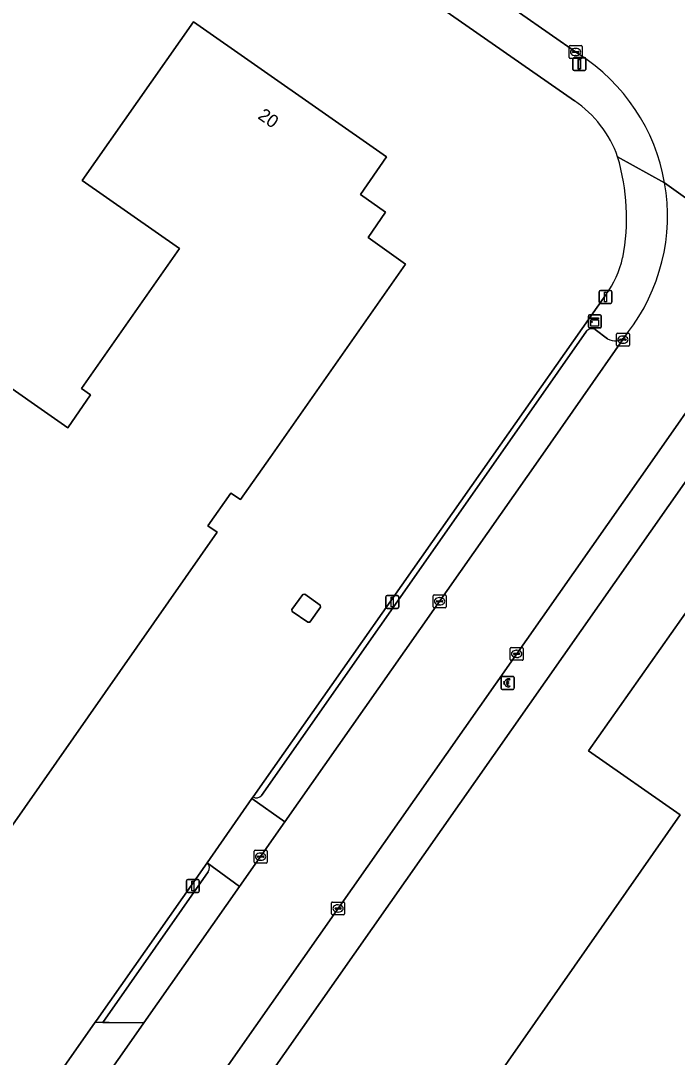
# Model space of a CAD drawing. Extents: x 155018 to 156648, y 383979 to 385733.
# Drawn here: x 155378.9 to 155429.7, y 384953.5 to 385033.8 of the extents above; entities that cross this region are included whole.
import ezdxf

# ---------------------------------------------------------------- set-up
doc = ezdxf.new("R2010")
doc.units = 0
for name, color, linetype in [('IMGEO_Betaalautomaat', 7, 'Continuous'), ('IMGEO_Erf', 7, 'Continuous'), ('IMGEO_Kast', 7, 'Continuous'), ('IMGEO_Kolk', 7, 'Continuous'), ('IMGEO_Lichtmast', 7, 'Continuous'), ('IMGEO_Pand', 7, 'Continuous'), ('IMGEO_Pand_nummerreeks', 7, 'Continuous'), ('IMGEO_Parkeervlak_open', 7, 'Continuous'), ('IMGEO_Rijbaan_lokaal_gesloten', 7, 'Continuous'), ('IMGEO_Rijbaan_lokaal_open', 7, 'Continuous'), ('IMGEO_Voetpad_open', 7, 'Continuous')]:
    doc.layers.add(name, color=color, linetype=linetype)

msp = doc.modelspace()

# ---------------------------------------------------------------- linework, layer by layer
at = {"layer": 'IMGEO_Betaalautomaat'}
for p, q in [((155416.064, 384982.106), (155416.064, 384982.947)), ((155416.064, 384982.947), (155416.064, 384982.106)), ((155416.139, 384983.03), (155416.98, 384983.03)), ((155416.98, 384983.03), (155416.139, 384983.03)), ((155416.726, 384982.835), (155416.709, 384982.735)), ((155417.063, 384982.956), (155417.063, 384982.115)), ((155417.063, 384982.115), (155417.063, 384982.956)), ((155416.989, 384982.031), (155416.148, 384982.031)), ((155416.148, 384982.031), (155416.989, 384982.031)), ((155416.347, 384982.494), (155416.347, 384982.562)), ((155416.468, 384982.562), (155416.468, 384982.494)), ((155416.713, 384982.329), (155416.735, 384982.242))]:
    msp.add_line(p, q, dxfattribs=at)
for points in [[(155416.347, 384982.562), (155416.278, 384982.562), (155416.278, 384982.631), (155416.357, 384982.631)], [(155416.352, 384982.425), (155416.278, 384982.425), (155416.278, 384982.494), (155416.347, 384982.494)], [(155416.479, 384982.631), (155416.626, 384982.631), (155416.626, 384982.562), (155416.468, 384982.562)], [(155416.468, 384982.494), (155416.626, 384982.494), (155416.626, 384982.425), (155416.482, 384982.425)]]:
    msp.add_lwpolyline(points, dxfattribs=at)
for centre, radius, start, end in [((155416.142, 384982.953), 0.0779, 92.4484, 184.28452), ((155416.142, 384982.953), 0.0779, 92.4484, 184.28452), ((155416.64, 384982.555), 0.293, 73.01398, 165.01395), ((155416.986, 384982.953), 0.0779, 2.4484, 94.28452), ((155416.986, 384982.953), 0.0779, 2.4484, 94.28452), ((155416.142, 384982.109), 0.0779, 182.4484, 274.28452), ((155416.142, 384982.109), 0.0779, 182.4484, 274.28452), ((155416.613, 384982.48), 0.267, 191.80956, 297.03891), ((155416.646, 384982.568), 0.179, 69.32359, 159.56827), ((155416.646, 384982.495), 0.179, 202.76249, 291.86925), ((155416.986, 384982.109), 0.0779, 272.4484, 4.28452), ((155416.986, 384982.109), 0.0779, 272.4484, 4.28452)]:
    msp.add_arc(centre, radius, start, end, dxfattribs=at)
at = {"layer": 'IMGEO_Erf'}
for points in [[(155421.752, 385027.617), (155394.996, 385046.278), (155391.028, 385049.046), (155385.591, 385052.838), (155385.399, 385052.961), (155380.151, 385056.63), (155341.349, 385083.758), (155335.658, 385087.641), (155324.962, 385095.154), (155317.041, 385100.717), (155292.001, 385118.303), (155289.287, 385120.198), (155288.53, 385120.608), (155288.137, 385120.826), (155288.024, 385120.665), (155281.331, 385125.336), (155281.524, 385125.635), (155276.133, 385129.546), (155243.348, 385152.362), (155212.561, 385173.841)], [(155415.322, 385000), (155424.161, 385012.596)], [(155435.235, 385005.097), (155431.663, 385000), (155395.301, 384948.119), (155392.871, 384944.656), (155386.964, 384936.206), (155382.993, 384930.585), (155380.633, 384927.147), (155378.001, 384923.366), (155376.2, 384920.796), (155354.955, 384890.532), (155337.874, 384866.058)], [(155327.011, 384874.232), (155360.91, 384922.726), (155360.915, 384922.733), (155375.747, 384943.951), (155375.951, 384943.821), (155379.854, 384949.392), (155384.652, 384956.241), (155384.747, 384956.376), (155393.303, 384968.589), (155396.774, 384973.585), (155396.869, 384973.702), (155415.322, 385000)]]:
    msp.add_lwpolyline(points, dxfattribs=at)
for points in [[(155351.349, 384984.37), (155362.289, 385000), (155370.017, 385011.042), (155382.518, 385002.292), (155384.294, 385004.83), (155383.582, 385005.329), (155391.174, 385016.176), (155383.643, 385021.448), (155392.242, 385033.743), (155407.202, 385023.273), (155405.168, 385020.366), (155407.118, 385018.987), (155405.763, 385017.027), (155408.659, 385014.971), (155398.182, 385000), (155395.894, 384996.73), (155395.145, 384997.227), (155393.369, 384994.694), (155394.096, 384994.197), (155375.417, 384967.495), (155365.992, 384954.131), (155341.937, 384971.002)], [(155437.272, 384901.403), (155412.162, 384919.023), (155417.316, 384926.358), (155404.257, 384935.52), (155429.931, 384972.307), (155422.839, 384977.259), (155438.817, 385000), (155439.816, 385001.422), (155441.823, 385000), (155445.207, 384997.603), (155444.284, 384997.18), (155444.973, 384993.255), (155452.396, 384994.446), (155452.453, 384994.103), (155450.711, 384993.78), (155463.948, 384984.474), (155458.937, 384977.31), (155471.068, 384968.794), (155464.079, 384958.829), (155473.162, 384952.461)], [(155399.897, 384988.059), (155399.873, 384988.22), (155400.711, 384989.382), (155400.863, 384989.396), (155402.049, 384988.541), (155402.076, 384988.399), (155401.268, 384987.233), (155401.109, 384987.228)]]:
    msp.add_lwpolyline(points, close=True, dxfattribs=at)
for centre, radius, start, end in [((155416.885, 385020.442), 8.67, 37.457, 55.84789), ((155416.874, 385020.421), 8.691, 19.17556, 37.52396), ((155409.507, 385018.585), 16.267, 348.93981, 16.76159), ((155418.417, 385016.955), 7.21, 322.8033, 348.06519)]:
    msp.add_arc(centre, radius, start, end, dxfattribs=at)
at = {"layer": 'IMGEO_Kast'}
for p, q in [((155422.817, 385010.103), (155422.817, 385010.944)), ((155422.817, 385010.944), (155422.817, 385010.103)), ((155422.892, 385011.028), (155423.733, 385011.028)), ((155423.733, 385011.028), (155422.892, 385011.028)), ((155423.817, 385010.953), (155423.817, 385010.112)), ((155423.817, 385010.112), (155423.817, 385010.953)), ((155423.742, 385010.028), (155422.901, 385010.028)), ((155422.901, 385010.028), (155423.742, 385010.028))]:
    msp.add_line(p, q, dxfattribs=at)
for points in [[(155423.012, 385010.818), (155423.612, 385010.818), (155423.612, 385010.733), (155423.012, 385010.733), (155423.012, 385010.818)], [(155423.012, 385010.643), (155423.612, 385010.643), (155423.612, 385010.154), (155423.012, 385010.154), (155423.012, 385010.643)]]:
    msp.add_lwpolyline(points, dxfattribs=at)
msp.add_circle((155423.096, 385010.492), 0.0377, dxfattribs=at)
for centre, start, end in [((155422.895, 385010.95), 92.4484, 184.28452), ((155422.895, 385010.95), 92.4484, 184.28452), ((155423.739, 385010.95), 2.4484, 94.28452), ((155423.739, 385010.95), 2.4484, 94.28452), ((155422.895, 385010.106), 182.4484, 274.28452), ((155422.895, 385010.106), 182.4484, 274.28452), ((155423.739, 385010.106), 272.4484, 4.28452), ((155423.739, 385010.106), 272.4484, 4.28452)]:
    msp.add_arc(centre, 0.0779, start, end, dxfattribs=at)
at = {"layer": 'IMGEO_Kolk'}
for p, q in [((155421.328, 385030.967), (155421.328, 385031.819)), ((155421.403, 385031.893), (155422.255, 385031.893)), ((155422.329, 385031.819), (155422.329, 385030.967)), ((155421.587, 385031.387), (155421.587, 385031.399)), ((155422.025, 385031.35), (155421.627, 385031.35)), ((155421.63, 385031.436), (155422.028, 385031.436)), ((155421.839, 385031.113), (155421.814, 385031.113)), ((155421.816, 385031.673), (155421.841, 385031.673)), ((155422.071, 385031.399), (155422.071, 385031.387)), ((155422.255, 385030.893), (155421.403, 385030.893)), ((155424.989, 385008.692), (155424.989, 385009.544)), ((155425.064, 385009.618), (155425.916, 385009.618)), ((155425.477, 385009.398), (155425.502, 385009.398)), ((155425.99, 385009.544), (155425.99, 385008.692)), ((155425.916, 385008.618), (155425.064, 385008.618)), ((155425.248, 385009.112), (155425.248, 385009.124)), ((155425.686, 385009.075), (155425.288, 385009.075)), ((155425.291, 385009.161), (155425.689, 385009.161)), ((155425.5, 385008.838), (155425.475, 385008.838)), ((155425.732, 385009.124), (155425.732, 385009.112)), ((155410.798, 384988.43), (155410.798, 384989.282)), ((155410.873, 384989.356), (155411.725, 384989.356)), ((155411.799, 384989.282), (155411.799, 384988.43)), ((155411.057, 384988.85), (155411.057, 384988.862)), ((155411.495, 384988.813), (155411.097, 384988.813)), ((155411.1, 384988.899), (155411.498, 384988.899)), ((155411.309, 384988.576), (155411.284, 384988.576)), ((155411.286, 384989.136), (155411.311, 384989.136)), ((155411.541, 384988.862), (155411.541, 384988.85)), ((155411.725, 384988.356), (155410.873, 384988.356)), ((155416.766, 384984.355), (155416.766, 384985.207)), ((155416.841, 384985.281), (155417.693, 384985.281)), ((155417.767, 384985.207), (155417.767, 384984.355)), ((155417.025, 384984.775), (155417.025, 384984.787)), ((155417.463, 384984.738), (155417.065, 384984.738)), ((155417.068, 384984.824), (155417.466, 384984.824)), ((155417.277, 384984.501), (155417.252, 384984.501)), ((155417.254, 384985.061), (155417.279, 384985.061)), ((155417.509, 384984.787), (155417.509, 384984.775)), ((155417.693, 384984.281), (155416.841, 384984.281)), ((155396.945, 384968.648), (155396.945, 384969.5)), ((155397.02, 384969.574), (155397.872, 384969.574)), ((155397.433, 384969.354), (155397.458, 384969.354)), ((155397.946, 384969.5), (155397.946, 384968.648)), ((155397.872, 384968.574), (155397.02, 384968.574)), ((155397.204, 384969.068), (155397.204, 384969.08)), ((155397.642, 384969.031), (155397.244, 384969.031)), ((155397.247, 384969.117), (155397.645, 384969.117)), ((155397.456, 384968.794), (155397.431, 384968.794)), ((155397.688, 384969.08), (155397.688, 384969.068)), ((155402.944, 384964.632), (155402.944, 384965.484)), ((155403.019, 384965.558), (155403.871, 384965.558)), ((155403.432, 384965.338), (155403.457, 384965.338)), ((155403.945, 384965.484), (155403.945, 384964.632)), ((155403.871, 384964.558), (155403.019, 384964.558)), ((155403.203, 384965.052), (155403.203, 384965.064)), ((155403.641, 384965.015), (155403.243, 384965.015)), ((155403.246, 384965.101), (155403.644, 384965.101)), ((155403.455, 384964.778), (155403.43, 384964.778)), ((155403.687, 384965.064), (155403.687, 384965.052))]:
    msp.add_line(p, q, dxfattribs=at)
for points in [[(155421.328, 385030.967), (155421.328, 385031.819)], [(155421.403, 385031.893), (155422.255, 385031.893)], [(155422.329, 385031.819), (155422.329, 385030.967)], [(155422.255, 385030.893), (155421.403, 385030.893)], [(155424.989, 385008.692), (155424.989, 385009.544)], [(155425.064, 385009.618), (155425.916, 385009.618)], [(155425.99, 385009.544), (155425.99, 385008.692)], [(155425.916, 385008.618), (155425.064, 385008.618)], [(155410.798, 384988.43), (155410.798, 384989.282)], [(155410.873, 384989.356), (155411.725, 384989.356)], [(155411.799, 384989.282), (155411.799, 384988.43)], [(155411.725, 384988.356), (155410.873, 384988.356)], [(155416.766, 384984.355), (155416.766, 384985.207)], [(155416.841, 384985.281), (155417.693, 384985.281)], [(155417.767, 384985.207), (155417.767, 384984.355)], [(155417.693, 384984.281), (155416.841, 384984.281)], [(155396.945, 384968.648), (155396.945, 384969.5)], [(155397.02, 384969.574), (155397.872, 384969.574)], [(155397.946, 384969.5), (155397.946, 384968.648)], [(155397.872, 384968.574), (155397.02, 384968.574)], [(155402.944, 384964.632), (155402.944, 384965.484)], [(155403.019, 384965.558), (155403.871, 384965.558)], [(155403.945, 384965.484), (155403.945, 384964.632)], [(155403.871, 384964.558), (155403.019, 384964.558)]]:
    msp.add_lwpolyline(points, dxfattribs=at)
for centre, radius, start, end in [((155421.405, 385031.817), 0.0765, 91.55205, 178.44795), ((155421.405, 385031.817), 0.0765, 91.55205, 178.44795), ((155422.253, 385031.817), 0.0765, 1.55205, 88.44795), ((155422.253, 385031.817), 0.0765, 1.55205, 88.44795), ((155421.405, 385030.969), 0.0765, 181.55205, 268.44795), ((155421.405, 385030.969), 0.0765, 181.55205, 268.44795), ((155421.627, 385031.396), 0.0403, 85.87752, 175.75265), ((155421.624, 385031.386), 0.0366, 178.93798, 274.71019), ((155422.028, 385031.393), 0.043, 264.86636, 352.45326), ((155422.032, 385031.398), 0.0386, 1.73085, 96.63898), ((155422.253, 385030.969), 0.0765, 271.55205, 358.44795), ((155422.253, 385030.969), 0.0765, 271.55205, 358.44795), ((155425.066, 385009.542), 0.0765, 91.55205, 178.44795), ((155425.066, 385009.542), 0.0765, 91.55205, 178.44795), ((155425.914, 385009.542), 0.0765, 1.55205, 88.44795), ((155425.914, 385009.542), 0.0765, 1.55205, 88.44795), ((155425.066, 385008.694), 0.0765, 181.55205, 268.44795), ((155425.066, 385008.694), 0.0765, 181.55205, 268.44795), ((155425.288, 385009.121), 0.0403, 85.87752, 175.75265), ((155425.285, 385009.111), 0.0366, 178.93798, 274.71019), ((155425.689, 385009.118), 0.043, 264.86636, 352.45326), ((155425.693, 385009.123), 0.0386, 1.73085, 96.63898), ((155425.914, 385008.694), 0.0765, 271.55205, 358.44795), ((155425.914, 385008.694), 0.0765, 271.55205, 358.44795), ((155410.875, 384989.28), 0.0765, 91.55205, 178.44795), ((155410.875, 384989.28), 0.0765, 91.55205, 178.44795), ((155411.723, 384989.28), 0.0765, 1.55205, 88.44795), ((155411.723, 384989.28), 0.0765, 1.55205, 88.44795), ((155410.875, 384988.432), 0.0765, 181.55205, 268.44795), ((155410.875, 384988.432), 0.0765, 181.55205, 268.44795), ((155411.097, 384988.859), 0.0403, 85.87752, 175.75265), ((155411.094, 384988.849), 0.0366, 178.93798, 274.71019), ((155411.498, 384988.856), 0.043, 264.86636, 352.45326), ((155411.502, 384988.861), 0.0386, 1.73085, 96.63898), ((155411.723, 384988.432), 0.0765, 271.55205, 358.44795), ((155411.723, 384988.432), 0.0765, 271.55205, 358.44795), ((155416.843, 384985.205), 0.0765, 91.55205, 178.44795), ((155416.843, 384985.205), 0.0765, 91.55205, 178.44795), ((155417.691, 384985.205), 0.0765, 1.55205, 88.44795), ((155417.691, 384985.205), 0.0765, 1.55205, 88.44795), ((155417.065, 384984.784), 0.0403, 85.87752, 175.75265), ((155417.062, 384984.774), 0.0366, 178.93798, 274.71019), ((155417.466, 384984.781), 0.043, 264.86636, 352.45326), ((155417.47, 384984.786), 0.0386, 1.73085, 96.63898), ((155416.843, 384984.357), 0.0765, 181.55205, 268.44795), ((155416.843, 384984.357), 0.0765, 181.55205, 268.44795), ((155417.691, 384984.357), 0.0765, 271.55205, 358.44795), ((155417.691, 384984.357), 0.0765, 271.55205, 358.44795), ((155397.022, 384969.498), 0.0765, 91.55205, 178.44795), ((155397.022, 384969.498), 0.0765, 91.55205, 178.44795), ((155397.87, 384969.498), 0.0765, 1.55205, 88.44795), ((155397.87, 384969.498), 0.0765, 1.55205, 88.44795), ((155397.022, 384968.65), 0.0765, 181.55205, 268.44795), ((155397.022, 384968.65), 0.0765, 181.55205, 268.44795), ((155397.244, 384969.077), 0.0403, 85.87752, 175.75265), ((155397.241, 384969.067), 0.0366, 178.93798, 274.71019), ((155397.645, 384969.074), 0.043, 264.86636, 352.45326), ((155397.649, 384969.079), 0.0386, 1.73085, 96.63898), ((155397.87, 384968.65), 0.0765, 271.55205, 358.44795), ((155397.87, 384968.65), 0.0765, 271.55205, 358.44795), ((155403.021, 384965.482), 0.0765, 91.55205, 178.44795), ((155403.021, 384965.482), 0.0765, 91.55205, 178.44795), ((155403.869, 384965.482), 0.0765, 1.55205, 88.44795), ((155403.869, 384965.482), 0.0765, 1.55205, 88.44795), ((155403.021, 384964.634), 0.0765, 181.55205, 268.44795), ((155403.021, 384964.634), 0.0765, 181.55205, 268.44795), ((155403.243, 384965.061), 0.0403, 85.87752, 175.75265), ((155403.24, 384965.051), 0.0366, 178.93798, 274.71019), ((155403.644, 384965.058), 0.043, 264.86636, 352.45326), ((155403.648, 384965.063), 0.0386, 1.73085, 96.63898), ((155403.869, 384964.634), 0.0765, 271.55205, 358.44795), ((155403.869, 384964.634), 0.0765, 271.55205, 358.44795)]:
    msp.add_arc(centre, radius, start, end, dxfattribs=at)
for centre, major_axis, ratio, start_param, end_param in [((155421.815, 385031.393), (-0.387, 0.002), 0.722429, 4.712389, 7.853982), ((155421.84, 385031.393), (-0.39, 0.002), 0.717154, 1.570796, 4.712389), ((155425.476, 385009.118), (-0.387, 0.002), 0.722429, 4.712389, 7.853982), ((155425.501, 385009.118), (-0.39, 0.002), 0.717154, 1.570796, 4.712389), ((155411.285, 384988.856), (-0.387, 0.002), 0.722429, 4.712389, 7.853982), ((155411.31, 384988.856), (-0.39, 0.002), 0.717154, 1.570796, 4.712389), ((155417.253, 384984.781), (-0.387, 0.002), 0.722429, 4.712389, 7.853982), ((155417.278, 384984.781), (-0.39, 0.002), 0.717154, 1.570796, 4.712389), ((155397.432, 384969.074), (-0.387, 0.002), 0.722429, 4.712389, 7.853982), ((155397.457, 384969.074), (-0.39, 0.002), 0.717154, 1.570796, 4.712389), ((155403.431, 384965.058), (-0.387, 0.002), 0.722429, 4.712389, 7.853982), ((155403.456, 384965.058), (-0.39, 0.002), 0.717154, 1.570796, 4.712389)]:
    msp.add_ellipse(centre, major_axis=major_axis, ratio=ratio, start_param=start_param, end_param=end_param, dxfattribs=at)
at = {"layer": 'IMGEO_Lichtmast'}
for p, q in [((155421.727, 385030.974), (155422.517, 385030.974)), ((155422.517, 385030.974), (155421.727, 385030.974)), ((155421.618, 385030.053), (155421.618, 385030.853)), ((155421.618, 385030.853), (155421.618, 385030.053)), ((155421.627, 385030.074), (155421.627, 385030.874)), ((155421.627, 385030.874), (155421.627, 385030.074)), ((155421.718, 385030.953), (155422.508, 385030.953)), ((155422.508, 385030.953), (155421.718, 385030.953)), ((155422.608, 385030.853), (155422.608, 385030.053)), ((155422.608, 385030.053), (155422.608, 385030.853)), ((155422.617, 385030.874), (155422.617, 385030.074)), ((155422.617, 385030.074), (155422.617, 385030.874)), ((155422.508, 385029.953), (155421.718, 385029.953)), ((155421.718, 385029.953), (155422.508, 385029.953)), ((155422.517, 385029.974), (155421.727, 385029.974)), ((155421.727, 385029.974), (155422.517, 385029.974)), ((155423.648, 385012.029), (155423.648, 385012.829)), ((155423.648, 385012.829), (155423.648, 385012.029)), ((155423.748, 385012.929), (155424.538, 385012.929)), ((155424.538, 385012.929), (155423.748, 385012.929)), ((155424.638, 385012.829), (155424.638, 385012.029)), ((155424.638, 385012.029), (155424.638, 385012.829)), ((155424.538, 385011.929), (155423.748, 385011.929)), ((155423.748, 385011.929), (155424.538, 385011.929)), ((155407.244, 384989.301), (155408.034, 384989.301)), ((155408.034, 384989.301), (155407.244, 384989.301)), ((155407.144, 384988.401), (155407.144, 384989.201)), ((155407.144, 384989.201), (155407.144, 384988.401)), ((155408.134, 384989.201), (155408.134, 384988.401)), ((155408.134, 384988.401), (155408.134, 384989.201)), ((155408.034, 384988.301), (155407.244, 384988.301)), ((155407.244, 384988.301), (155408.034, 384988.301)), ((155391.715, 384966.401), (155391.715, 384967.201)), ((155391.715, 384967.201), (155391.715, 384966.401)), ((155391.815, 384967.301), (155392.605, 384967.301)), ((155392.605, 384967.301), (155391.815, 384967.301)), ((155392.705, 384967.201), (155392.705, 384966.401)), ((155392.705, 384966.401), (155392.705, 384967.201)), ((155392.605, 384966.301), (155391.815, 384966.301)), ((155391.815, 384966.301), (155392.605, 384966.301))]:
    msp.add_line(p, q, dxfattribs=at)
for points in [[(155422.038, 385030.828), (155422.188, 385030.828), (155422.188, 385030.078), (155422.038, 385030.078), (155422.038, 385030.828)], [(155422.047, 385030.849), (155422.197, 385030.849), (155422.197, 385030.099), (155422.047, 385030.099), (155422.047, 385030.849)], [(155424.068, 385012.804), (155424.218, 385012.804), (155424.218, 385012.054), (155424.068, 385012.054), (155424.068, 385012.804)], [(155407.564, 384989.176), (155407.714, 384989.176), (155407.714, 384988.426), (155407.564, 384988.426), (155407.564, 384989.176)], [(155392.135, 384967.176), (155392.285, 384967.176), (155392.285, 384966.426), (155392.135, 384966.426), (155392.135, 384967.176)]]:
    msp.add_lwpolyline(points, dxfattribs=at)
for centre, start, end in [((155421.727, 385030.874), 90, 180), ((155421.727, 385030.874), 90, 180), ((155422.517, 385030.874), 0, 90), ((155422.517, 385030.874), 360, 90), ((155421.718, 385030.853), 90, 180), ((155421.718, 385030.853), 90, 180), ((155422.508, 385030.853), 0, 90), ((155422.508, 385030.853), 360, 90), ((155421.718, 385030.053), 180, 270), ((155421.718, 385030.053), 180, 270), ((155421.727, 385030.074), 180, 270), ((155421.727, 385030.074), 180, 270), ((155422.508, 385030.053), 270, 0), ((155422.508, 385030.053), 270, 0), ((155422.517, 385030.074), 270, 0), ((155422.517, 385030.074), 270, 0), ((155423.748, 385012.829), 90, 180), ((155423.748, 385012.829), 90, 180), ((155424.538, 385012.829), 0, 90), ((155424.538, 385012.829), 360, 90), ((155423.748, 385012.029), 180, 270), ((155423.748, 385012.029), 180, 270), ((155424.538, 385012.029), 270, 0), ((155424.538, 385012.029), 270, 0), ((155407.244, 384989.201), 90, 180), ((155407.244, 384989.201), 90, 180), ((155408.034, 384989.201), 0, 90), ((155408.034, 384989.201), 360, 90), ((155407.244, 384988.401), 180, 270), ((155407.244, 384988.401), 180, 270), ((155408.034, 384988.401), 270, 0), ((155408.034, 384988.401), 270, 0), ((155391.815, 384967.201), 90, 180), ((155391.815, 384967.201), 90, 180), ((155392.605, 384967.201), 0, 90), ((155392.605, 384967.201), 360, 90), ((155391.815, 384966.401), 180, 270), ((155391.815, 384966.401), 180, 270), ((155392.605, 384966.401), 270, 0), ((155392.605, 384966.401), 270, 0)]:
    msp.add_arc(centre, 0.1, start, end, dxfattribs=at)
at = {"layer": 'IMGEO_Pand'}
for points in [[(155392.242, 385033.743), (155383.643, 385021.448), (155391.174, 385016.176), (155383.582, 385005.329), (155384.294, 385004.83), (155382.518, 385002.292), (155370.017, 385011.042), (155362.289, 385000), (155351.349, 384984.37), (155341.937, 384971.002), (155365.992, 384954.131), (155375.417, 384967.495), (155394.096, 384994.197), (155393.369, 384994.694), (155395.145, 384997.227), (155395.894, 384996.73), (155398.182, 385000), (155408.659, 385014.971), (155405.763, 385017.027), (155407.118, 385018.987), (155405.168, 385020.366), (155407.202, 385023.273)], [(155437.272, 384901.403), (155473.162, 384952.461), (155464.079, 384958.829), (155471.068, 384968.794), (155458.937, 384977.31), (155463.948, 384984.474), (155450.711, 384993.78), (155452.453, 384994.103), (155452.396, 384994.446), (155444.973, 384993.255), (155444.284, 384997.18), (155445.207, 384997.603), (155441.823, 385000), (155439.816, 385001.422), (155438.817, 385000), (155422.839, 384977.259), (155429.931, 384972.307), (155404.257, 384935.52), (155417.316, 384926.358), (155412.162, 384919.023)], [(155401.109, 384987.228), (155401.268, 384987.233), (155402.076, 384988.399), (155402.049, 384988.541), (155400.863, 384989.396), (155400.711, 384989.382), (155399.873, 384988.22), (155399.897, 384988.059)]]:
    msp.add_lwpolyline(points, close=True, dxfattribs=at)
at = {"layer": 'IMGEO_Parkeervlak_open'}
for points in [[(155396.869, 384973.702), (155396.774, 384973.585), (155399.323, 384971.769), (155419.101, 385000), (155425.671, 385009.382)], [(155422.675, 385009.78), (155415.834, 385000), (155397.519, 384973.816)], [(155424.303, 385009.188), (155423.337, 385009.894)], [(155395.806, 384966.749), (155393.303, 384968.589)], [(155393.391, 384967.906), (155385.225, 384956.234), (155385.733, 384956.227), (155388.41, 384956.193), (155395.806, 384966.749)]]:
    msp.add_lwpolyline(points, dxfattribs=at)
for centre, radius, start, end in [((155423.075, 385009.436), 0.528, 60.24729, 139.29434), ((155424.874, 385010.079), 1.058, 237.32742, 318.8155), ((155397.132, 384974.115), 0.49, 237.5709, 322.32435), ((155393.001, 384968.203), 0.49, 322.7419, 51.94156)]:
    msp.add_arc(centre, radius, start, end, dxfattribs=at)
at = {"layer": 'IMGEO_Rijbaan_lokaal_gesloten'}
for points in [[(155254.18, 385148.516), (155259.887, 385144.522), (155262.142, 385142.929), (155267.693, 385139.068), (155276.485, 385133.016), (155284.974, 385127.104), (155291.112, 385122.808), (155293.027, 385121.5), (155293.867, 385120.844), (155318.912, 385103.338), (155326.847, 385097.791), (155337.534, 385090.321), (155343.17, 385086.381), (155381.966, 385059.233), (155386.945, 385055.783), (155387.447, 385055.409), (155392.859, 385051.629), (155396.824, 385048.861), (155422.076, 385031.226)], [(155428.721, 385021.264), (155441.576, 385012.058)], [(155441.576, 385012.058), (155428.721, 385021.264)], [(155425.852, 385009.637), (155425.671, 385009.382), (155419.101, 385000), (155399.323, 384971.769), (155395.806, 384966.749), (155388.41, 384956.193), (155388.176, 384955.859), (155381.158, 384945.842), (155378.515, 384942.069), (155378.441, 384941.964), (155361.769, 384918.146)], [(155384.463, 384937.948), (155390.393, 384946.374), (155394.958, 384952.938), (155397.073, 384955.962), (155427.929, 385000), (155432.193, 385006.088)]]:
    msp.add_lwpolyline(points, dxfattribs=at)
for centre, radius, start, end in [((155414.095, 385018.705), 14.848, 9.924, 57.48533), ((155414.099, 385018.704), 14.844, 322.34869, 9.92925)]:
    msp.add_arc(centre, radius, start, end, dxfattribs=at)
at = {"layer": 'IMGEO_Rijbaan_lokaal_open'}
for points in [[(155399.323, 384971.769), (155396.774, 384973.585), (155393.303, 384968.589), (155395.806, 384966.749)], [(155388.176, 384955.859), (155388.41, 384956.193), (155385.733, 384956.227), (155385.225, 384956.234), (155384.652, 384956.241), (155379.854, 384949.392), (155380.055, 384948.845), (155381.158, 384945.842)]]:
    msp.add_lwpolyline(points, close=True, dxfattribs=at)
at = {"layer": 'IMGEO_Voetpad_open'}
for points in [[(155422.076, 385031.226), (155396.824, 385048.861), (155394.996, 385046.278), (155421.752, 385027.617)], [(155428.721, 385021.264), (155425.083, 385023.276)], [(155425.083, 385023.276), (155428.721, 385021.264)], [(155424.161, 385012.596), (155415.322, 385000), (155396.869, 384973.702)], [(155397.519, 384973.816), (155415.834, 385000), (155422.675, 385009.78)], [(155423.337, 385009.894), (155424.303, 385009.188)], [(155425.671, 385009.382), (155425.852, 385009.637)], [(155432.193, 385006.088), (155427.929, 385000), (155397.073, 384955.962), (155394.958, 384952.938), (155395.301, 384948.119), (155431.663, 385000)], [(155393.303, 384968.589), (155384.747, 384956.376), (155384.652, 384956.241), (155385.225, 384956.234), (155393.391, 384967.906)]]:
    msp.add_lwpolyline(points, dxfattribs=at)
for centre, radius, start, end in [((155414.095, 385018.705), 14.848, 9.924, 57.48533), ((155416.885, 385020.442), 8.67, 37.457, 55.84789), ((155416.874, 385020.421), 8.691, 19.17556, 37.52396), ((155409.507, 385018.585), 16.267, 348.93981, 16.76159), ((155414.099, 385018.704), 14.844, 322.34869, 9.92925), ((155418.417, 385016.955), 7.21, 322.8033, 348.06519), ((155423.075, 385009.436), 0.528, 60.24729, 139.29434), ((155424.874, 385010.079), 1.058, 237.32742, 318.8155), ((155397.132, 384974.115), 0.49, 237.5709, 322.32435), ((155393.001, 384968.203), 0.49, 322.7419, 51.94156)]:
    msp.add_arc(centre, radius, start, end, dxfattribs=at)

# ---------------------------------------------------------------- texts
at = {"layer": 'IMGEO_Pand_nummerreeks'}
msp.add_text('20', height=1, rotation=325.01312, dxfattribs=at).set_placement((155397.167, 385026.293))

doc.saveas('drawing.dxf')
